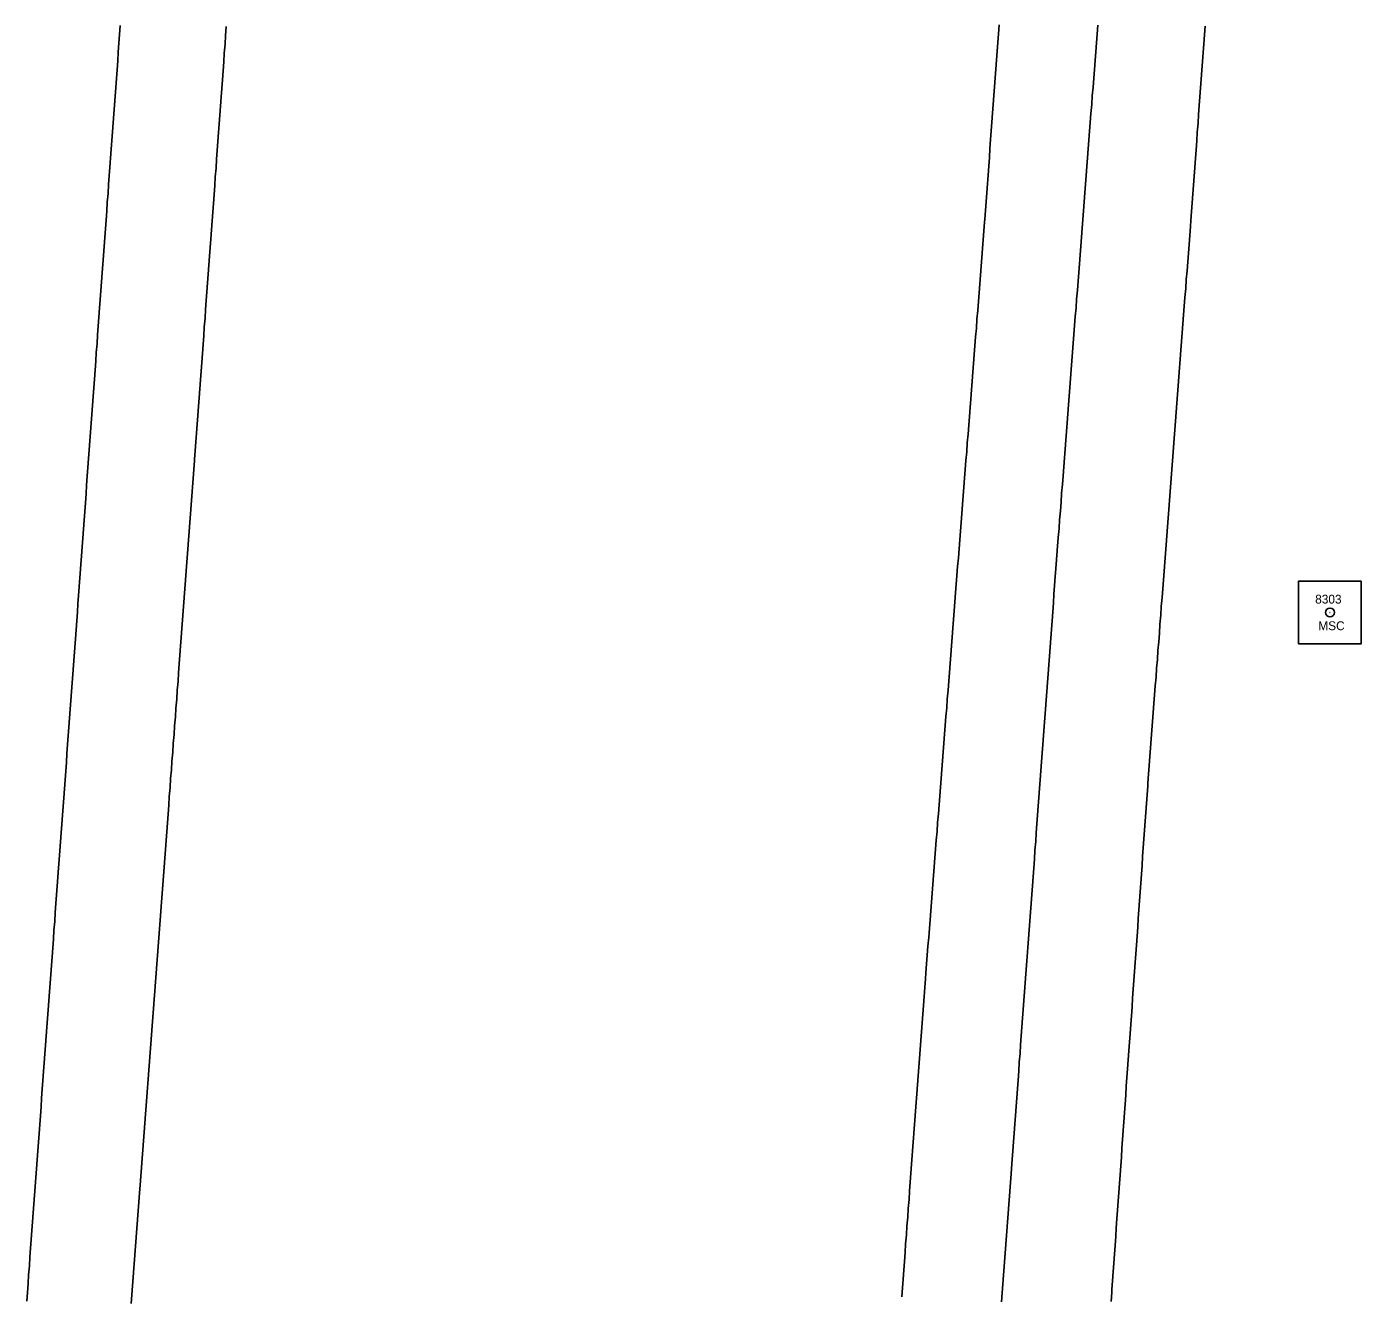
# Model space of a CAD drawing. Extents: x 205929 to 2357175, y -1785700 to 846739.
# Drawn here: x 2023387.5 to 2023538.2, y 809074.3 to 809217.5 of the extents above; entities that cross this region are included whole.
import ezdxf

# ---------------------------------------------------------------- set-up
doc = ezdxf.new("R2010")
doc.units = 0
for name, color, linetype in [('RD_HC_Survey', 7, 'Continuous'), ('RD_HC_txCode', 7, 'Continuous'), ('RD_Sketch1', 7, 'Continuous'), ('RD_SMD_Locator', 7, 'Continuous')]:
    doc.layers.add(name, color=color, linetype=linetype)

msp = doc.modelspace()

# ---------------------------------------------------------------- linework, layer by layer
at = {"layer": 'RD_HC_Survey'}
msp.add_lwpolyline([(2023538.16, 809154.95), (2023531.09, 809154.95), (2023531.09, 809147.87), (2023538.16, 809147.87)], close=True, dxfattribs=at)
msp.add_circle((2023534.63, 809151.41), 0.5, dxfattribs=at)
at = {"layer": 'RD_Sketch1'}
for points in [[(2023398.07, 809217.65), (2023398, 809216.65), (2023397.92, 809215.66), (2023397.85, 809214.66), (2023397.78, 809213.66), (2023397.71, 809212.66), (2023397.63, 809211.67), (2023397.56, 809210.67), (2023397.49, 809209.67), (2023397.41, 809208.68), (2023397.34, 809207.68), (2023397.27, 809206.68), (2023397.2, 809205.68), (2023397.12, 809204.69), (2023397.05, 809203.69), (2023396.98, 809202.69), (2023396.9, 809201.69), (2023396.83, 809200.7), (2023396.76, 809199.7), (2023396.69, 809198.7), (2023396.69, 809198.7), (2023396.61, 809197.71), (2023396.54, 809196.71), (2023396.47, 809195.71), (2023396.39, 809194.71), (2023396.32, 809193.72), (2023396.25, 809192.72), (2023396.18, 809191.72), (2023396.1, 809190.72), (2023396.03, 809189.73), (2023395.96, 809188.73), (2023395.88, 809187.73), (2023395.81, 809186.74), (2023395.74, 809185.74), (2023395.66, 809184.74), (2023395.59, 809183.74), (2023395.52, 809182.75), (2023395.45, 809181.75), (2023395.37, 809180.75), (2023395.3, 809179.76), (2023395.23, 809178.76), (2023395.15, 809177.76), (2023395.08, 809176.76), (2023395.01, 809175.77), (2023394.94, 809174.77), (2023394.86, 809173.77), (2023394.79, 809172.77), (2023394.72, 809171.78), (2023394.64, 809170.78), (2023394.57, 809169.78), (2023394.5, 809168.79), (2023394.43, 809167.79), (2023394.35, 809166.79), (2023394.28, 809165.79), (2023394.21, 809164.8), (2023394.13, 809163.8), (2023394.06, 809162.8), (2023393.99, 809161.81), (2023393.92, 809160.81), (2023393.84, 809159.81), (2023393.77, 809158.81), (2023393.7, 809157.82), (2023393.62, 809156.82), (2023393.55, 809155.82), (2023393.48, 809154.82), (2023393.41, 809153.83), (2023393.33, 809152.83), (2023393.3, 809152.44), (2023393.23, 809151.45), (2023393.16, 809150.45), (2023393.09, 809149.45), (2023393.01, 809148.45), (2023392.94, 809147.46), (2023392.87, 809146.46), (2023392.79, 809145.46), (2023392.72, 809144.46), (2023392.65, 809143.47), (2023392.57, 809142.47), (2023392.5, 809141.47), (2023392.43, 809140.48), (2023392.35, 809139.48), (2023392.28, 809138.48), (2023392.21, 809137.48), (2023392.13, 809136.49), (2023392.06, 809135.49), (2023392.06, 809135.49), (2023391.99, 809134.49), (2023391.91, 809133.5), (2023391.84, 809132.5), (2023391.77, 809131.5), (2023391.69, 809130.5), (2023391.62, 809129.51), (2023391.55, 809128.51), (2023391.47, 809127.51), (2023391.4, 809126.52), (2023391.33, 809125.52), (2023391.25, 809124.52), (2023391.18, 809123.52), (2023391.11, 809122.53), (2023391.03, 809121.53), (2023390.96, 809120.53), (2023390.89, 809119.53), (2023390.81, 809118.54), (2023390.74, 809117.54), (2023390.67, 809116.54), (2023390.59, 809115.55), (2023390.52, 809114.55), (2023390.45, 809113.55), (2023390.37, 809112.55), (2023390.3, 809111.56), (2023390.23, 809110.56), (2023390.15, 809109.56), (2023390.08, 809108.57), (2023390.01, 809107.57), (2023389.93, 809106.57), (2023389.86, 809105.57), (2023389.79, 809104.58), (2023389.71, 809103.58), (2023389.64, 809102.58), (2023389.57, 809101.59), (2023389.49, 809100.59), (2023389.42, 809099.59), (2023389.35, 809098.59), (2023389.27, 809097.6), (2023389.2, 809096.6), (2023389.13, 809095.6), (2023389.05, 809094.6), (2023388.98, 809093.61), (2023388.91, 809092.61), (2023388.83, 809091.61), (2023388.76, 809090.62), (2023388.69, 809089.62), (2023388.61, 809088.62), (2023388.54, 809087.62), (2023388.47, 809086.63), (2023388.39, 809085.63), (2023388.32, 809084.63), (2023388.25, 809083.64), (2023388.17, 809082.64), (2023388.1, 809081.64), (2023388.03, 809080.64), (2023387.95, 809079.65), (2023387.88, 809078.65), (2023387.81, 809077.65), (2023387.73, 809076.66), (2023387.66, 809075.66), (2023387.59, 809074.66), (2023387.51, 809073.66)], [(2023410.04, 809217.54), (2023409.97, 809216.54), (2023409.9, 809215.54), (2023409.82, 809214.54), (2023409.75, 809213.55), (2023409.68, 809212.55), (2023409.61, 809211.55), (2023409.53, 809210.56), (2023409.46, 809209.56), (2023409.39, 809208.56), (2023409.31, 809207.56), (2023409.24, 809206.57), (2023409.17, 809205.57), (2023409.09, 809204.57), (2023409.02, 809203.57), (2023408.95, 809202.58), (2023408.88, 809201.58), (2023408.8, 809200.58), (2023408.73, 809199.59), (2023408.66, 809198.59), (2023408.58, 809197.59), (2023408.58, 809197.59), (2023408.51, 809196.59), (2023408.44, 809195.6), (2023408.37, 809194.6), (2023408.29, 809193.6), (2023408.22, 809192.6), (2023408.15, 809191.61), (2023408.07, 809190.61), (2023408, 809189.61), (2023407.93, 809188.62), (2023407.86, 809187.62), (2023407.78, 809186.62), (2023407.71, 809185.62), (2023407.64, 809184.63), (2023407.56, 809183.63), (2023407.49, 809182.63), (2023407.42, 809181.64), (2023407.35, 809180.64), (2023407.27, 809179.64), (2023407.2, 809178.64), (2023407.13, 809177.65), (2023407.05, 809176.65), (2023406.98, 809175.65), (2023406.91, 809174.65), (2023406.83, 809173.66), (2023406.76, 809172.66), (2023406.69, 809171.66), (2023406.62, 809170.67), (2023406.54, 809169.67), (2023406.47, 809168.67), (2023406.46, 809168.54), (2023406.39, 809167.54), (2023406.31, 809166.55), (2023406.24, 809165.55), (2023406.16, 809164.55), (2023406.09, 809163.55), (2023406.01, 809162.56), (2023405.94, 809161.56), (2023405.86, 809160.56), (2023405.79, 809159.57), (2023405.71, 809158.57), (2023405.64, 809157.57), (2023405.56, 809156.58), (2023405.49, 809155.58), (2023405.41, 809154.58), (2023405.34, 809153.58), (2023405.26, 809152.59), (2023405.19, 809151.59), (2023405.11, 809150.59), (2023405.04, 809149.6), (2023404.96, 809148.6), (2023404.89, 809147.6), (2023404.81, 809146.6), (2023404.74, 809145.61), (2023404.66, 809144.61), (2023404.59, 809143.61), (2023404.51, 809142.62), (2023404.44, 809141.62), (2023404.36, 809140.62), (2023404.29, 809139.62), (2023404.21, 809138.63), (2023404.14, 809137.63), (2023404.06, 809136.63), (2023403.99, 809135.64), (2023403.91, 809134.64), (2023403.91, 809134.64), (2023403.84, 809133.64), (2023403.76, 809132.65), (2023403.69, 809131.65), (2023403.61, 809130.65), (2023403.54, 809129.65), (2023403.47, 809128.66), (2023403.39, 809127.66), (2023403.32, 809126.66), (2023403.24, 809125.67), (2023403.17, 809124.67), (2023403.09, 809123.67), (2023403.02, 809122.67), (2023402.94, 809121.68), (2023402.87, 809120.68), (2023402.79, 809119.68), (2023402.72, 809118.69), (2023402.64, 809117.69), (2023402.57, 809116.69), (2023402.49, 809115.69), (2023402.42, 809114.7), (2023402.34, 809113.7), (2023402.27, 809112.7), (2023402.19, 809111.71), (2023402.12, 809110.71), (2023402.04, 809109.71), (2023401.97, 809108.71), (2023401.89, 809107.72), (2023401.82, 809106.72), (2023401.74, 809105.72), (2023401.67, 809104.73), (2023401.59, 809103.73), (2023401.52, 809102.73), (2023401.44, 809101.74), (2023401.37, 809100.74), (2023401.29, 809099.74), (2023401.22, 809098.74), (2023401.14, 809097.75), (2023401.07, 809096.75), (2023400.99, 809095.75), (2023400.92, 809094.76), (2023400.84, 809093.76), (2023400.77, 809092.76), (2023400.69, 809091.76), (2023400.62, 809090.77), (2023400.54, 809089.77), (2023400.47, 809088.77), (2023400.39, 809087.78), (2023400.32, 809086.78), (2023400.29, 809086.35), (2023400.21, 809085.36), (2023400.14, 809084.36), (2023400.06, 809083.36), (2023399.99, 809082.37), (2023399.91, 809081.37), (2023399.84, 809080.37), (2023399.76, 809079.37), (2023399.68, 809078.38), (2023399.61, 809077.38), (2023399.53, 809076.38), (2023399.46, 809075.39), (2023399.38, 809074.39), (2023399.31, 809073.39)], [(2023497.27, 809217.74), (2023497.2, 809216.74), (2023497.13, 809215.75), (2023497.05, 809214.75), (2023496.98, 809213.75), (2023496.91, 809212.75), (2023496.83, 809211.76), (2023496.76, 809210.76), (2023496.69, 809209.76), (2023496.61, 809208.76), (2023496.54, 809207.77), (2023496.47, 809206.77), (2023496.4, 809205.77), (2023496.32, 809204.78), (2023496.25, 809203.78), (2023496.18, 809202.78), (2023496.1, 809201.78), (2023496.03, 809200.79), (2023495.96, 809199.79), (2023495.88, 809198.79), (2023495.81, 809197.79), (2023495.74, 809196.8), (2023495.66, 809195.8), (2023495.64, 809195.47), (2023495.56, 809194.48), (2023495.49, 809193.48), (2023495.41, 809192.48), (2023495.33, 809191.49), (2023495.25, 809190.49), (2023495.17, 809189.49), (2023495.1, 809188.5), (2023495.02, 809187.5), (2023494.94, 809186.5), (2023494.94, 809186.5), (2023494.86, 809185.51), (2023494.78, 809184.51), (2023494.71, 809183.51), (2023494.63, 809182.52), (2023494.55, 809181.52), (2023494.47, 809180.52), (2023494.39, 809179.52), (2023494.32, 809178.53), (2023494.24, 809177.53), (2023494.16, 809176.53), (2023494.08, 809175.54), (2023494, 809174.54), (2023493.93, 809173.54), (2023493.85, 809172.55), (2023493.77, 809171.55), (2023493.69, 809170.55), (2023493.62, 809169.56), (2023493.54, 809168.56), (2023493.46, 809167.56), (2023493.38, 809166.57), (2023493.3, 809165.57), (2023493.23, 809164.57), (2023493.15, 809163.58), (2023493.07, 809162.58), (2023492.99, 809161.58), (2023492.91, 809160.58), (2023492.84, 809159.59), (2023492.76, 809158.59), (2023492.68, 809157.59), (2023492.6, 809156.6), (2023492.52, 809155.6), (2023492.45, 809154.6), (2023492.37, 809153.61), (2023492.29, 809152.61), (2023492.21, 809151.61), (2023492.14, 809150.62), (2023492.06, 809149.62), (2023491.98, 809148.62), (2023491.9, 809147.63), (2023491.82, 809146.63), (2023491.75, 809145.63), (2023491.67, 809144.63), (2023491.59, 809143.64), (2023491.51, 809142.64), (2023491.43, 809141.64), (2023491.36, 809140.65), (2023491.28, 809139.65), (2023491.2, 809138.65), (2023491.12, 809137.66), (2023491.04, 809136.66), (2023490.97, 809135.66), (2023490.89, 809134.67), (2023490.81, 809133.67), (2023490.73, 809132.67), (2023490.66, 809131.68), (2023490.58, 809130.68), (2023490.5, 809129.68), (2023490.42, 809128.69), (2023490.34, 809127.69), (2023490.27, 809126.69), (2023490.19, 809125.69), (2023490.11, 809124.7), (2023490.03, 809123.7), (2023489.95, 809122.7), (2023489.95, 809122.7), (2023489.88, 809121.71), (2023489.8, 809120.71), (2023489.72, 809119.71), (2023489.64, 809118.72), (2023489.56, 809117.72), (2023489.49, 809116.72), (2023489.41, 809115.73), (2023489.33, 809114.73), (2023489.25, 809113.73), (2023489.17, 809112.74), (2023489.1, 809111.74), (2023489.02, 809110.74), (2023488.97, 809110.06), (2023488.89, 809109.06), (2023488.82, 809108.06), (2023488.74, 809107.06), (2023488.67, 809106.07), (2023488.59, 809105.07), (2023488.52, 809104.07), (2023488.44, 809103.08), (2023488.37, 809102.08), (2023488.3, 809101.08), (2023488.22, 809100.08), (2023488.15, 809099.09), (2023488.07, 809098.09), (2023488, 809097.09), (2023487.92, 809096.1), (2023487.85, 809095.1), (2023487.78, 809094.1), (2023487.7, 809093.11), (2023487.63, 809092.11), (2023487.55, 809091.11), (2023487.48, 809090.11), (2023487.4, 809089.12), (2023487.33, 809088.12), (2023487.25, 809087.12), (2023487.18, 809086.13), (2023487.11, 809085.13), (2023487.03, 809084.13), (2023486.96, 809083.14), (2023486.88, 809082.14), (2023486.81, 809081.14), (2023486.73, 809080.14), (2023486.66, 809079.15), (2023486.59, 809078.15), (2023486.51, 809077.15), (2023486.44, 809076.16), (2023486.36, 809075.16), (2023486.29, 809074.16)], [(2023508.42, 809217.7), (2023508.34, 809216.7), (2023508.26, 809215.7), (2023508.19, 809214.71), (2023508.11, 809213.71), (2023508.03, 809212.71), (2023507.96, 809211.72), (2023507.88, 809210.72), (2023507.8, 809209.72), (2023507.73, 809208.73), (2023507.65, 809207.73), (2023507.57, 809206.73), (2023507.49, 809205.73), (2023507.42, 809204.74), (2023507.34, 809203.74), (2023507.26, 809202.74), (2023507.19, 809201.75), (2023507.11, 809200.75), (2023507.03, 809199.75), (2023506.96, 809198.76), (2023506.88, 809197.76), (2023506.8, 809196.76), (2023506.73, 809195.77), (2023506.65, 809194.77), (2023506.57, 809193.77), (2023506.5, 809192.77), (2023506.42, 809191.78), (2023506.34, 809190.78), (2023506.27, 809189.78), (2023506.19, 809188.79), (2023506.11, 809187.79), (2023506.03, 809186.79), (2023505.96, 809185.8), (2023505.96, 809185.8), (2023505.88, 809184.8), (2023505.8, 809183.8), (2023505.73, 809182.8), (2023505.65, 809181.81), (2023505.57, 809180.81), (2023505.5, 809179.81), (2023505.42, 809178.82), (2023505.34, 809177.82), (2023505.27, 809176.82), (2023505.19, 809175.83), (2023505.11, 809174.83), (2023505.04, 809173.83), (2023504.96, 809172.83), (2023504.88, 809171.84), (2023504.81, 809170.84), (2023504.73, 809169.84), (2023504.65, 809168.85), (2023504.57, 809167.85), (2023504.5, 809166.85), (2023504.42, 809165.86), (2023504.34, 809164.86), (2023504.27, 809163.86), (2023504.19, 809162.87), (2023504.11, 809161.87), (2023504.04, 809160.87), (2023503.96, 809159.87), (2023503.88, 809158.88), (2023503.81, 809157.88), (2023503.73, 809156.88), (2023503.65, 809155.89), (2023503.62, 809155.47), (2023503.55, 809154.47), (2023503.47, 809153.47), (2023503.4, 809152.48), (2023503.33, 809151.48), (2023503.25, 809150.48), (2023503.18, 809149.48), (2023503.1, 809148.49), (2023503.03, 809147.49), (2023502.96, 809146.49), (2023502.88, 809145.5), (2023502.81, 809144.5), (2023502.74, 809143.5), (2023502.66, 809142.5), (2023502.59, 809141.51), (2023502.51, 809140.51), (2023502.44, 809139.51), (2023502.37, 809138.52), (2023502.29, 809137.52), (2023502.22, 809136.52), (2023502.14, 809135.52), (2023502.07, 809134.53), (2023502, 809133.53), (2023501.92, 809132.53), (2023501.85, 809131.54), (2023501.78, 809130.54), (2023501.7, 809129.54), (2023501.63, 809128.54), (2023501.55, 809127.55), (2023501.48, 809126.55), (2023501.41, 809125.55), (2023501.33, 809124.56), (2023501.26, 809123.56), (2023501.19, 809122.56), (2023501.19, 809122.56), (2023501.11, 809121.56), (2023501.04, 809120.57), (2023500.96, 809119.57), (2023500.89, 809118.57), (2023500.82, 809117.58), (2023500.74, 809116.58), (2023500.67, 809115.58), (2023500.6, 809114.58), (2023500.52, 809113.59), (2023500.45, 809112.59), (2023500.37, 809111.59), (2023500.3, 809110.6), (2023500.23, 809109.6), (2023500.15, 809108.6), (2023500.08, 809107.6), (2023500.01, 809106.61), (2023499.93, 809105.61), (2023499.86, 809104.61), (2023499.78, 809103.62), (2023499.71, 809102.62), (2023499.64, 809101.62), (2023499.56, 809100.63), (2023499.49, 809099.63), (2023499.42, 809098.63), (2023499.34, 809097.63), (2023499.27, 809096.64), (2023499.19, 809095.64), (2023499.12, 809094.64), (2023499.05, 809093.65), (2023498.97, 809092.65), (2023498.9, 809091.65), (2023498.82, 809090.65), (2023498.75, 809089.66), (2023498.68, 809088.66), (2023498.67, 809088.56), (2023498.6, 809087.56), (2023498.52, 809086.56), (2023498.45, 809085.57), (2023498.37, 809084.57), (2023498.3, 809083.57), (2023498.22, 809082.58), (2023498.15, 809081.58), (2023498.07, 809080.58), (2023498, 809079.58), (2023497.92, 809078.59), (2023497.85, 809077.59), (2023497.78, 809076.59), (2023497.7, 809075.6), (2023497.63, 809074.6), (2023497.55, 809073.6)], [(2023520.53, 809217.6), (2023520.46, 809216.6), (2023520.39, 809215.6), (2023520.31, 809214.61), (2023520.24, 809213.61), (2023520.17, 809212.61), (2023520.09, 809211.62), (2023520.02, 809210.62), (2023519.95, 809209.62), (2023519.87, 809208.62), (2023519.8, 809207.63), (2023519.73, 809206.63), (2023519.65, 809205.63), (2023519.58, 809204.64), (2023519.51, 809203.64), (2023519.43, 809202.64), (2023519.36, 809201.64), (2023519.29, 809200.65), (2023519.22, 809199.65), (2023519.14, 809198.65), (2023519.07, 809197.66), (2023519, 809196.66), (2023518.92, 809195.66), (2023518.87, 809194.96), (2023518.79, 809193.96), (2023518.72, 809192.96), (2023518.64, 809191.97), (2023518.57, 809190.97), (2023518.49, 809189.97), (2023518.41, 809188.98), (2023518.34, 809187.98), (2023518.26, 809186.98), (2023518.18, 809185.98), (2023518.11, 809184.99), (2023518.03, 809183.99), (2023517.96, 809182.99), (2023517.88, 809182), (2023517.8, 809181), (2023517.73, 809180), (2023517.65, 809179.01), (2023517.58, 809178.01), (2023517.5, 809177.01), (2023517.42, 809176.01), (2023517.35, 809175.02), (2023517.27, 809174.02), (2023517.19, 809173.02), (2023517.12, 809172.03), (2023517.04, 809171.03), (2023516.97, 809170.03), (2023516.89, 809169.03), (2023516.81, 809168.04), (2023516.74, 809167.04), (2023516.66, 809166.04), (2023516.58, 809165.05), (2023516.51, 809164.05), (2023516.43, 809163.05), (2023516.36, 809162.06), (2023516.28, 809161.06), (2023516.2, 809160.06), (2023516.2, 809160.06), (2023516.13, 809159.06), (2023516.05, 809158.07), (2023515.98, 809157.07), (2023515.9, 809156.07), (2023515.82, 809155.08), (2023515.75, 809154.08), (2023515.67, 809153.08), (2023515.59, 809152.09), (2023515.52, 809151.09), (2023515.44, 809150.09), (2023515.37, 809149.09), (2023515.29, 809148.1), (2023515.21, 809147.1), (2023515.14, 809146.1), (2023515.06, 809145.11), (2023514.99, 809144.11), (2023514.91, 809143.11), (2023514.83, 809142.12), (2023514.76, 809141.12), (2023514.68, 809140.12), (2023514.6, 809139.12), (2023514.53, 809138.13), (2023514.45, 809137.13), (2023514.38, 809136.13), (2023514.3, 809135.14), (2023514.22, 809134.14), (2023514.15, 809133.14), (2023514.07, 809132.15), (2023514.05, 809131.82), (2023513.98, 809130.83), (2023513.91, 809129.83), (2023513.83, 809128.83), (2023513.76, 809127.84), (2023513.69, 809126.84), (2023513.62, 809125.84), (2023513.55, 809124.84), (2023513.48, 809123.85), (2023513.41, 809122.85), (2023513.34, 809121.85), (2023513.27, 809120.85), (2023513.2, 809119.86), (2023513.13, 809118.86), (2023513.06, 809117.86), (2023512.99, 809116.86), (2023512.92, 809115.87), (2023512.85, 809114.87), (2023512.77, 809113.87), (2023512.7, 809112.88), (2023512.63, 809111.88), (2023512.56, 809110.88), (2023512.49, 809109.88), (2023512.42, 809108.89), (2023512.35, 809107.89), (2023512.28, 809106.89), (2023512.21, 809105.89), (2023512.14, 809104.9), (2023512.07, 809103.9), (2023512, 809102.9), (2023511.93, 809101.91), (2023511.86, 809100.91), (2023511.79, 809099.91), (2023511.71, 809098.91), (2023511.64, 809097.92), (2023511.57, 809096.92), (2023511.57, 809096.92), (2023511.5, 809095.92), (2023511.43, 809094.92), (2023511.36, 809093.93), (2023511.29, 809092.93), (2023511.22, 809091.93), (2023511.15, 809090.93), (2023511.08, 809089.94), (2023511.01, 809088.94), (2023510.94, 809087.94), (2023510.87, 809086.95), (2023510.8, 809085.95), (2023510.73, 809084.95), (2023510.65, 809083.95), (2023510.58, 809082.96), (2023510.51, 809081.96), (2023510.44, 809080.96), (2023510.37, 809079.96), (2023510.3, 809078.97), (2023510.23, 809077.97), (2023510.16, 809076.97), (2023510.09, 809075.97), (2023510.02, 809074.98), (2023510, 809074.65), (2023509.94, 809073.65)]]:
    msp.add_lwpolyline(points, dxfattribs=at)
at = {"layer": 'RD_SMD_Locator'}
msp.add_circle((2023534.63, 809151.41), 0.001, dxfattribs=at)

# ---------------------------------------------------------------- texts
at = {"layer": 'RD_HC_txCode'}
for s, p in [('8303', (2023532.96, 809152.41)), ('MSC', (2023533.31, 809149.41))]:
    msp.add_text(s, height=1, dxfattribs=at).set_placement(p)

doc.saveas('drawing.dxf')
